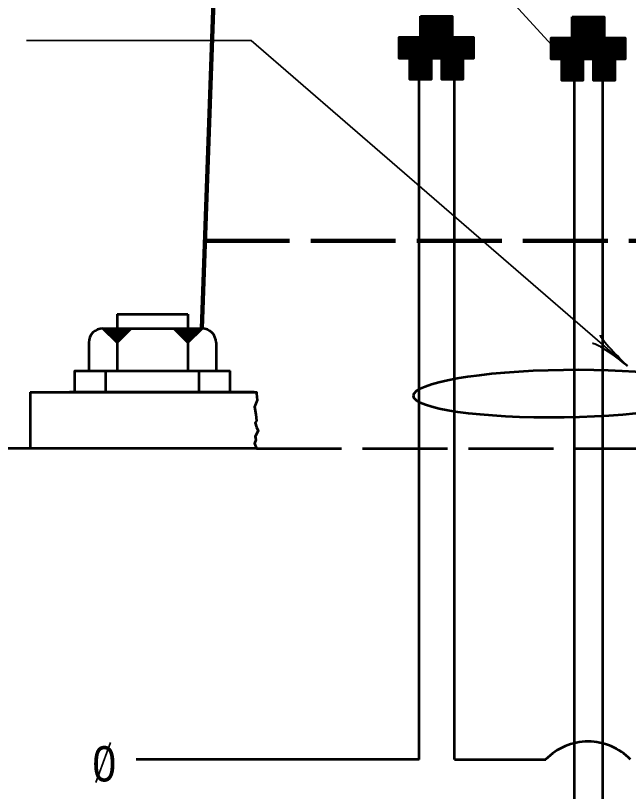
# Model space of a CAD drawing. Extents: x -153 to 527, y -247 to 194.
# Drawn here: x 76.9 to 120.3, y 47.5 to 102.4 of the extents above; entities that cross this region are included whole.
import ezdxf

# ---------------------------------------------------------------- set-up
doc = ezdxf.new("R2010")
doc.units = 0
doc.linetypes.add('LONG_DASHED', pattern=[7.5, 6, -1.5])
doc.layers.add('1', color=7, linetype='Continuous', lineweight=53)

msp = doc.modelspace()

# ---------------------------------------------------------------- linework, layer by layer
at = {"layer": '1', "lineweight": 90}
msp.add_line((90.13, 80.231), (92.956, 161.182), dxfattribs=at)
at = {"layer": '1', "lineweight": 35}
for p, q in [((86.516, 131.404), (114.867, 100.269)), ((93.621, 100.614), (77.712, 100.614)), ((93.621, 100.614), (120.211, 77.581)), ((83.665, 50.928), (82.634, 48.096))]:
    msp.add_line(p, q, dxfattribs=at)
at = {"layer": '1'}
for p, q in [((105.586, 102.186), (107.836, 102.186)), ((116.321, 102.136), (118.571, 102.136)), ((105.586, 102.036), (107.836, 102.036)), ((105.586, 101.861), (107.836, 101.861)), ((105.586, 101.71), (107.836, 101.71)), ((116.321, 101.985), (118.571, 101.985)), ((116.321, 101.81), (118.571, 101.81)), ((116.321, 101.659), (118.571, 101.659)), ((105.586, 101.56), (107.836, 101.56)), ((105.586, 101.384), (107.836, 101.384)), ((105.586, 101.234), (107.836, 101.234)), ((105.586, 101.058), (107.836, 101.058)), ((116.321, 101.509), (118.571, 101.509)), ((116.321, 101.333), (118.571, 101.333)), ((116.321, 101.183), (118.571, 101.183)), ((104.086, 100.732), (105.586, 100.732)), ((104.086, 100.632), (105.586, 100.632)), ((104.086, 100.507), (105.586, 100.507)), ((105.586, 100.883), (107.836, 100.883)), ((105.586, 100.732), (107.836, 100.732)), ((105.586, 100.557), (107.836, 100.557)), ((107.836, 100.782), (109.336, 100.782)), ((107.836, 100.657), (109.336, 100.657)), ((107.836, 100.557), (109.336, 100.557)), ((114.821, 100.682), (116.321, 100.682)), ((114.821, 100.581), (116.321, 100.581)), ((116.321, 101.007), (118.571, 101.007)), ((116.321, 100.832), (118.571, 100.832)), ((116.321, 100.682), (118.571, 100.682)), ((116.321, 100.506), (118.571, 100.506)), ((118.571, 100.732), (120.071, 100.732)), ((118.571, 100.606), (120.071, 100.606)), ((118.571, 100.506), (120.071, 100.506)), ((104.086, 100.356), (105.586, 100.356)), ((104.086, 100.231), (105.586, 100.231)), ((104.086, 100.055), (105.586, 100.055)), ((105.586, 100.431), (107.836, 100.431)), ((105.586, 100.331), (107.836, 100.331)), ((105.586, 100.256), (107.836, 100.256)), ((105.586, 100.206), (107.836, 100.206)), ((105.586, 100.131), (107.836, 100.131)), ((105.586, 99.98), (107.836, 99.98)), ((107.836, 100.406), (109.336, 100.406)), ((107.836, 100.231), (109.336, 100.231)), ((107.836, 100.105), (109.336, 100.105)), ((107.836, 99.955), (109.336, 99.955)), ((114.821, 100.456), (116.321, 100.456)), ((114.821, 100.305), (116.321, 100.305)), ((114.821, 100.18), (116.321, 100.18)), ((114.821, 100.005), (116.321, 100.005)), ((116.321, 100.381), (118.571, 100.381)), ((116.321, 100.28), (118.571, 100.28)), ((116.321, 100.205), (118.571, 100.205)), ((116.321, 100.155), (118.571, 100.155)), ((116.321, 100.08), (118.571, 100.08)), ((118.571, 100.356), (120.071, 100.356)), ((118.571, 100.18), (120.071, 100.18)), ((118.571, 100.055), (120.071, 100.055)), ((104.086, 99.88), (105.586, 99.88)), ((104.086, 99.78), (105.586, 99.78)), ((104.086, 99.654), (105.586, 99.654)), ((104.086, 99.554), (105.586, 99.554)), ((104.086, 99.403), (105.586, 99.403)), ((105.586, 99.905), (107.836, 99.905)), ((105.586, 99.729), (107.836, 99.729)), ((105.586, 99.579), (107.836, 99.579)), ((105.586, 99.454), (107.836, 99.454)), ((107.836, 99.83), (109.336, 99.83)), ((107.836, 99.704), (109.336, 99.704)), ((107.836, 99.579), (109.336, 99.579)), ((107.836, 99.428), (109.336, 99.428)), ((114.821, 99.829), (116.321, 99.829)), ((114.821, 99.729), (116.321, 99.729)), ((114.821, 99.603), (116.321, 99.603)), ((114.821, 99.503), (116.321, 99.503)), ((116.321, 99.929), (118.571, 99.929)), ((116.321, 99.854), (118.571, 99.854)), ((116.321, 99.679), (118.571, 99.679)), ((116.321, 99.528), (118.571, 99.528)), ((116.321, 99.403), (118.571, 99.403)), ((118.571, 99.904), (120.071, 99.904)), ((118.571, 99.779), (120.071, 99.779)), ((118.571, 99.654), (120.071, 99.654)), ((118.571, 99.528), (120.071, 99.528)), ((106.336, 99.328), (104.836, 99.328)), ((106.336, 99.303), (104.836, 99.303)), ((106.336, 99.228), (104.836, 99.228)), ((106.336, 99.128), (104.836, 99.128)), ((106.336, 99.027), (104.836, 99.027)), ((106.336, 98.952), (104.836, 98.952)), ((106.336, 98.902), (104.836, 98.902)), ((106.336, 98.852), (104.836, 98.852)), ((108.586, 99.378), (107.086, 99.378)), ((108.586, 99.328), (107.086, 99.328)), ((108.586, 99.278), (107.086, 99.278)), ((108.586, 99.228), (107.086, 99.228)), ((108.586, 99.153), (107.086, 99.153)), ((108.586, 99.078), (107.086, 99.078)), ((108.586, 99.027), (107.086, 99.027)), ((108.586, 98.977), (107.086, 98.977)), ((108.586, 98.902), (107.086, 98.902)), ((108.586, 98.852), (107.086, 98.852)), ((114.821, 99.353), (116.321, 99.353)), ((117.071, 99.278), (115.571, 99.278)), ((117.071, 99.252), (115.571, 99.252)), ((117.071, 99.177), (115.571, 99.177)), ((117.071, 99.077), (115.571, 99.077)), ((117.071, 98.977), (115.571, 98.977)), ((117.071, 98.901), (115.571, 98.901)), ((117.071, 98.851), (115.571, 98.851)), ((119.321, 99.328), (117.821, 99.328)), ((119.321, 99.278), (117.821, 99.278)), ((119.321, 99.227), (117.821, 99.227)), ((119.321, 99.177), (117.821, 99.177)), ((119.321, 99.102), (117.821, 99.102)), ((119.321, 99.027), (117.821, 99.027)), ((119.321, 98.977), (117.821, 98.977)), ((119.321, 98.926), (117.821, 98.926)), ((119.321, 98.851), (117.821, 98.851)), ((118.571, 99.378), (120.071, 99.378)), ((106.336, 98.752), (104.836, 98.752)), ((106.336, 98.676), (104.836, 98.676)), ((106.336, 98.576), (104.836, 98.576)), ((106.336, 98.476), (104.836, 98.476)), ((106.336, 98.35), (104.836, 98.35)), ((108.586, 98.777), (107.086, 98.777)), ((108.586, 98.727), (107.086, 98.727)), ((108.586, 98.701), (107.086, 98.701)), ((108.586, 98.651), (107.086, 98.651)), ((108.586, 98.626), (107.086, 98.626)), ((108.586, 98.576), (107.086, 98.576)), ((108.586, 98.526), (107.086, 98.526)), ((108.586, 98.476), (107.086, 98.476)), ((108.586, 98.401), (107.086, 98.401)), ((108.586, 98.325), (107.086, 98.325)), ((117.071, 98.801), (115.571, 98.801)), ((117.071, 98.701), (115.571, 98.701)), ((117.071, 98.626), (115.571, 98.626)), ((117.071, 98.525), (115.571, 98.525)), ((117.071, 98.425), (115.571, 98.425)), ((117.071, 98.3), (115.571, 98.3)), ((119.321, 98.801), (117.821, 98.801)), ((119.321, 98.726), (117.821, 98.726)), ((119.321, 98.676), (117.821, 98.676)), ((119.321, 98.651), (117.821, 98.651)), ((119.321, 98.6), (117.821, 98.6)), ((119.321, 98.575), (117.821, 98.575)), ((119.321, 98.525), (117.821, 98.525)), ((119.321, 98.475), (117.821, 98.475)), ((119.321, 98.425), (117.821, 98.425)), ((119.321, 98.35), (117.821, 98.35)), ((106.336, 98.25), (104.836, 98.25)), ((106.336, 98.15), (104.836, 98.15)), ((106.336, 98.049), (104.836, 98.049)), ((106.336, 97.949), (104.836, 97.949)), ((105.488, 49.731), (105.488, 97.837)), ((108.586, 98.25), (107.086, 98.25)), ((108.586, 98.2), (107.086, 98.2)), ((108.586, 98.15), (107.086, 98.15)), ((108.586, 98.1), (107.086, 98.1)), ((108.586, 98.025), (107.086, 98.025)), ((108.586, 97.999), (107.086, 97.999)), ((107.988, 49.731), (107.988, 97.837)), ((117.071, 98.199), (115.571, 98.199)), ((117.071, 98.099), (115.571, 98.099)), ((117.071, 97.999), (115.571, 97.999)), ((117.071, 97.898), (115.571, 97.898)), ((116.488, 43.731), (116.488, 97.786)), ((119.321, 98.275), (117.821, 98.275)), ((119.321, 98.199), (117.821, 98.199)), ((119.321, 98.149), (117.821, 98.149)), ((119.321, 98.099), (117.821, 98.099)), ((119.321, 98.049), (117.821, 98.049)), ((119.321, 97.974), (117.821, 97.974)), ((119.321, 97.949), (117.821, 97.949)), ((118.488, 43.731), (118.488, 97.786)), ((84.13, 81.231), (84.13, 77.231)), ((84.13, 81.231), (89.13, 81.231)), ((89.13, 81.231), (89.13, 77.231)), ((83.13, 80.231), (90.13, 80.231)), ((84.13, 79.231), (83.13, 80.231)), ((83.212, 80.149), (83.295, 80.231)), ((83.225, 80.135), (83.308, 80.218)), ((83.242, 80.118), (83.325, 80.201)), ((83.246, 80.115), (83.328, 80.198)), ((83.25, 80.11), (83.333, 80.193)), ((83.252, 80.109), (83.334, 80.191)), ((83.255, 80.106), (83.337, 80.188)), ((83.261, 80.1), (83.392, 80.231)), ((83.264, 80.097), (83.398, 80.231)), ((83.272, 80.089), (83.414, 80.231)), ((83.275, 80.086), (83.42, 80.231)), ((83.287, 80.073), (83.445, 80.231)), ((83.294, 80.067), (83.458, 80.231)), ((83.303, 80.058), (83.477, 80.231)), ((83.311, 80.05), (83.492, 80.231)), ((83.322, 80.039), (83.514, 80.231)), ((83.333, 80.028), (83.536, 80.231)), ((83.337, 80.023), (83.545, 80.231)), ((83.345, 80.015), (83.561, 80.231)), ((83.35, 80.011), (83.571, 80.231)), ((83.35, 80.011), (83.571, 80.231)), ((83.356, 80.004), (83.583, 80.231)), ((83.361, 80), (83.593, 80.231)), ((83.37, 79.99), (83.611, 80.231)), ((83.382, 79.979), (83.633, 80.231)), ((83.391, 79.97), (83.652, 80.231)), ((83.394, 79.967), (83.659, 80.231)), ((83.408, 79.953), (83.687, 80.231)), ((83.419, 79.942), (83.709, 80.231)), ((83.428, 79.932), (83.727, 80.231)), ((83.436, 79.924), (83.743, 80.231)), ((83.438, 79.923), (83.746, 80.231)), ((83.449, 79.912), (83.768, 80.231)), ((83.457, 79.904), (83.784, 80.231)), ((83.465, 79.896), (83.799, 80.231)), ((83.471, 79.89), (83.812, 80.231)), ((83.476, 79.885), (83.822, 80.231)), ((83.486, 79.874), (83.843, 80.231)), ((83.491, 79.87), (83.853, 80.231)), ((83.496, 79.865), (83.862, 80.231)), ((83.51, 79.851), (83.89, 80.231)), ((83.513, 79.848), (83.897, 80.231)), ((83.516, 79.844), (83.903, 80.231)), ((83.524, 79.837), (83.919, 80.231)), ((83.535, 79.826), (83.941, 80.231)), ((83.54, 79.821), (83.95, 80.231)), ((83.546, 79.815), (83.963, 80.231)), ((83.551, 79.81), (83.972, 80.231)), ((83.557, 79.804), (83.984, 80.231)), ((83.56, 79.801), (83.991, 80.231)), ((83.566, 79.794), (84.003, 80.231)), ((83.579, 79.782), (84.028, 80.231)), ((83.588, 79.772), (84.047, 80.231)), ((83.591, 79.769), (84.053, 80.231)), ((83.606, 79.755), (84.082, 80.231)), ((83.606, 79.755), (84.082, 80.231)), ((83.609, 79.752), (84.088, 80.231)), ((83.612, 79.749), (84.094, 80.231)), ((83.615, 79.746), (84.1, 80.231)), ((83.621, 79.739), (84.113, 80.231)), ((83.626, 79.735), (84.122, 80.231)), ((83.626, 79.735), (84.122, 80.231)), ((83.634, 79.727), (84.138, 80.231)), ((83.643, 79.718), (84.157, 80.231)), ((83.648, 79.713), (84.166, 80.231)), ((83.653, 79.708), (84.176, 80.231)), ((83.656, 79.705), (84.182, 80.231)), ((83.657, 79.703), (84.185, 80.231)), ((83.66, 79.7), (84.191, 80.231)), ((83.671, 79.689), (84.213, 80.231)), ((83.684, 79.677), (84.238, 80.231)), ((83.692, 79.669), (84.254, 80.231)), ((83.698, 79.663), (84.267, 80.231)), ((83.709, 79.652), (84.289, 80.231)), ((83.714, 79.647), (84.298, 80.231)), ((83.714, 79.647), (84.298, 80.231)), ((83.717, 79.644), (84.304, 80.231)), ((83.717, 79.644), (84.304, 80.231)), ((83.723, 79.638), (84.317, 80.231)), ((83.73, 79.631), (84.329, 80.231)), ((83.737, 79.623), (84.345, 80.231)), ((83.75, 79.611), (84.37, 80.231)), ((83.756, 79.605), (84.383, 80.231)), ((83.762, 79.598), (84.395, 80.231)), ((83.764, 79.597), (84.398, 80.231)), ((83.77, 79.59), (84.411, 80.231)), ((83.78, 79.581), (84.429, 80.231)), ((83.789, 79.572), (84.448, 80.231)), ((83.797, 79.564), (84.464, 80.231)), ((83.801, 79.559), (84.473, 80.231)), ((83.806, 79.555), (84.483, 80.231)), ((83.809, 79.551), (84.489, 80.231)), ((83.82, 79.54), (84.511, 80.231)), ((83.825, 79.536), (84.52, 80.231)), ((83.827, 79.534), (84.468, 80.174)), ((83.828, 79.533), (84.527, 80.231)), ((83.836, 79.525), (84.542, 80.231)), ((83.839, 79.522), (84.548, 80.231)), ((83.839, 79.522), (84.549, 80.231)), ((83.842, 79.518), (84.555, 80.231)), ((83.852, 79.509), (84.574, 80.231)), ((83.866, 79.495), (84.602, 80.231)), ((83.871, 79.49), (84.612, 80.231)), ((83.882, 79.479), (84.633, 80.231)), ((83.888, 79.473), (84.646, 80.231)), ((83.897, 79.464), (84.665, 80.231)), ((83.902, 79.459), (84.674, 80.231)), ((83.907, 79.454), (84.684, 80.231)), ((83.911, 79.45), (84.693, 80.231)), ((83.918, 79.443), (84.706, 80.231)), ((83.925, 79.435), (84.721, 80.231)), ((83.936, 79.424), (84.743, 80.231)), ((83.939, 79.421), (84.749, 80.231)), ((83.952, 79.409), (84.774, 80.231)), ((83.961, 79.399), (84.793, 80.231)), ((83.966, 79.395), (84.803, 80.231)), ((83.969, 79.391), (84.809, 80.231)), ((83.982, 79.379), (84.834, 80.231)), ((83.991, 79.37), (84.853, 80.231)), ((83.996, 79.365), (84.862, 80.231)), ((84.002, 79.359), (84.874, 80.231)), ((84.005, 79.355), (84.881, 80.231)), ((84.008, 79.352), (84.887, 80.231)), ((84.018, 79.343), (84.906, 80.231)), ((84.019, 79.341), (84.909, 80.231)), ((84.027, 79.334), (84.924, 80.231)), ((84.027, 79.334), (84.925, 80.231)), ((84.038, 79.322), (84.947, 80.231)), ((84.043, 79.318), (84.956, 80.231)), ((84.054, 79.307), (84.978, 80.231)), ((84.055, 79.305), (84.981, 80.231)), ((84.071, 79.29), (85.013, 80.231)), ((84.077, 79.283), (85.025, 80.231)), ((84.09, 79.271), (85.05, 80.231)), ((84.102, 79.258), (85.075, 80.231)), ((84.102, 79.258), (85.075, 80.231)), ((84.115, 79.246), (85.1, 80.231)), ((84.13, 79.231), (85.13, 80.231)), ((89.13, 79.231), (88.13, 80.231)), ((89.136, 79.228), (88.136, 80.228)), ((88.149, 80.216), (88.164, 80.231)), ((88.163, 80.202), (88.192, 80.231)), ((88.175, 80.189), (88.217, 80.231)), ((88.181, 80.183), (88.23, 80.231)), ((88.191, 80.174), (88.248, 80.231)), ((88.202, 80.163), (88.27, 80.231)), ((88.211, 80.153), (88.289, 80.231)), ((88.216, 80.148), (88.298, 80.231)), ((88.219, 80.145), (88.302, 80.228)), ((88.232, 80.133), (88.33, 80.231)), ((88.239, 80.125), (88.322, 80.207)), ((88.242, 80.122), (88.325, 80.204)), ((88.249, 80.116), (88.364, 80.231)), ((88.252, 80.112), (88.371, 80.231)), ((88.252, 80.112), (88.335, 80.194)), ((88.257, 80.107), (88.34, 80.19)), ((88.268, 80.097), (88.402, 80.231)), ((88.274, 80.09), (88.415, 80.231)), ((88.282, 80.083), (88.43, 80.231)), ((88.288, 80.076), (88.443, 80.231)), ((88.294, 80.07), (88.452, 80.228)), ((88.301, 80.064), (88.468, 80.231)), ((88.311, 80.053), (88.49, 80.231)), ((88.322, 80.042), (88.512, 80.231)), ((88.324, 80.04), (88.515, 80.231)), ((88.327, 80.037), (88.521, 80.231)), ((88.329, 80.036), (88.524, 80.231)), ((88.332, 80.032), (88.531, 80.231)), ((88.337, 80.027), (88.541, 80.231)), ((88.344, 80.02), (88.552, 80.228)), ((88.357, 80.007), (88.577, 80.228)), ((88.377, 79.987), (88.618, 80.228)), ((88.382, 79.982), (88.631, 80.231)), ((88.388, 79.976), (88.64, 80.228)), ((88.393, 79.971), (88.653, 80.231)), ((88.395, 79.97), (88.656, 80.231)), ((88.401, 79.964), (88.668, 80.231)), ((88.404, 79.96), (88.675, 80.231)), ((88.415, 79.949), (88.697, 80.231)), ((88.415, 79.949), (88.694, 80.228)), ((88.42, 79.945), (88.706, 80.231)), ((88.426, 79.938), (88.719, 80.231)), ((88.429, 79.935), (88.725, 80.231)), ((88.44, 79.924), (88.747, 80.231)), ((88.445, 79.92), (88.756, 80.231)), ((88.446, 79.918), (88.759, 80.231)), ((88.456, 79.909), (88.778, 80.231)), ((88.459, 79.906), (88.785, 80.231)), ((88.464, 79.901), (88.794, 80.231)), ((88.464, 79.901), (88.753, 80.19)), ((88.478, 79.887), (88.822, 80.231)), ((88.486, 79.879), (88.838, 80.231)), ((88.489, 79.876), (88.844, 80.231)), ((88.495, 79.87), (88.857, 80.231)), ((88.498, 79.866), (88.86, 80.228)), ((88.501, 79.863), (88.869, 80.231)), ((88.503, 79.862), (88.869, 80.228)), ((88.52, 79.844), (88.903, 80.228)), ((88.529, 79.835), (88.926, 80.231)), ((88.536, 79.829), (88.938, 80.231)), ((88.544, 79.821), (88.954, 80.231)), ((88.547, 79.818), (88.957, 80.228)), ((88.557, 79.807), (88.978, 80.228)), ((88.558, 79.807), (88.982, 80.231)), ((88.569, 79.796), (89.004, 80.231)), ((88.573, 79.791), (89.01, 80.228)), ((88.58, 79.785), (89.026, 80.231)), ((88.586, 79.779), (89.035, 80.228)), ((88.592, 79.772), (89.051, 80.231)), ((88.6, 79.764), (89.067, 80.231)), ((88.606, 79.758), (89.079, 80.231)), ((88.609, 79.755), (89.086, 80.231)), ((88.612, 79.752), (89.092, 80.231)), ((88.616, 79.749), (89.095, 80.228)), ((88.62, 79.744), (89.099, 80.223)), ((88.622, 79.743), (89.11, 80.231)), ((88.633, 79.732), (89.129, 80.228)), ((88.633, 79.732), (89.129, 80.228)), ((88.636, 79.728), (89.139, 80.231)), ((88.641, 79.724), (89.148, 80.231)), ((88.645, 79.719), (89.158, 80.231)), ((88.658, 79.706), (89.183, 80.231)), ((88.659, 79.705), (89.186, 80.231)), ((88.669, 79.695), (89.205, 80.231)), ((88.678, 79.686), (89.22, 80.228)), ((88.685, 79.68), (89.236, 80.231)), ((88.694, 79.67), (89.255, 80.231)), ((88.699, 79.666), (89.264, 80.231)), ((88.705, 79.659), (89.273, 80.228)), ((88.707, 79.658), (89.28, 80.231)), ((88.713, 79.651), (89.293, 80.231)), ((88.721, 79.644), (89.308, 80.231)), ((88.721, 79.644), (89.304, 80.228)), ((88.722, 79.642), (89.311, 80.231)), ((88.73, 79.634), (89.327, 80.231)), ((88.735, 79.63), (89.336, 80.231)), ((88.736, 79.628), (89.336, 80.228)), ((88.741, 79.623), (89.349, 80.231)), ((88.741, 79.623), (89.349, 80.231)), ((88.744, 79.62), (89.352, 80.228)), ((88.746, 79.619), (89.358, 80.231)), ((88.747, 79.617), (89.361, 80.231)), ((88.755, 79.609), (89.377, 80.231)), ((88.771, 79.594), (89.405, 80.228)), ((88.777, 79.587), (89.418, 80.228)), ((88.779, 79.586), (89.424, 80.231)), ((88.785, 79.579), (89.435, 80.229)), ((88.786, 79.578), (89.436, 80.228)), ((88.798, 79.567), (89.447, 80.217)), ((88.807, 79.557), (89.457, 80.207)), ((88.808, 79.556), (89.48, 80.228)), ((88.829, 79.535), (89.479, 80.185)), ((88.835, 79.529), (89.534, 80.228)), ((88.841, 79.523), (89.55, 80.231)), ((88.846, 79.519), (89.555, 80.228)), ((88.854, 79.51), (89.575, 80.231)), ((88.859, 79.506), (89.581, 80.228)), ((88.865, 79.499), (89.597, 80.231)), ((88.87, 79.495), (89.606, 80.231)), ((88.881, 79.484), (89.628, 80.231)), ((88.893, 79.471), (89.653, 80.231)), ((88.895, 79.47), (89.653, 80.228)), ((88.903, 79.462), (89.675, 80.234)), ((88.904, 79.46), (89.671, 80.228)), ((88.907, 79.457), (89.681, 80.231)), ((88.909, 79.456), (89.681, 80.228)), ((88.912, 79.453), (89.691, 80.231)), ((88.923, 79.441), (89.713, 80.231)), ((88.932, 79.432), (89.728, 80.228)), ((88.942, 79.423), (89.75, 80.231)), ((88.943, 79.421), (89.75, 80.228)), ((88.946, 79.418), (89.756, 80.228)), ((88.948, 79.416), (89.763, 80.231)), ((88.959, 79.406), (89.781, 80.228)), ((88.961, 79.404), (89.788, 80.231)), ((88.968, 79.396), (89.8, 80.228)), ((88.973, 79.391), (89.809, 80.228)), ((88.976, 79.388), (89.816, 80.228)), ((88.978, 79.387), (89.822, 80.231)), ((88.989, 79.376), (89.841, 80.228)), ((88.998, 79.366), (89.86, 80.228)), ((89.001, 79.363), (89.869, 80.231)), ((89.009, 79.356), (89.881, 80.228)), ((89.011, 79.354), (89.883, 80.226)), ((89.014, 79.351), (89.886, 80.223)), ((89.023, 79.341), (89.896, 80.213)), ((89.025, 79.34), (89.913, 80.228)), ((89.026, 79.338), (89.916, 80.228)), ((89.034, 79.331), (89.931, 80.228)), ((89.044, 79.321), (89.916, 80.193)), ((89.045, 79.319), (89.954, 80.228)), ((89.048, 79.316), (89.921, 80.188)), ((89.05, 79.315), (89.963, 80.228)), ((89.053, 79.311), (89.925, 80.184)), ((89.061, 79.304), (89.985, 80.228)), ((89.061, 79.303), (89.933, 80.176)), ((89.061, 79.303), (89.933, 80.176)), ((89.062, 79.302), (89.988, 80.228)), ((89.062, 79.302), (89.935, 80.174)), ((89.064, 79.3), (89.995, 80.231)), ((89.067, 79.297), (89.94, 80.17)), ((89.075, 79.289), (90.017, 80.231)), ((89.078, 79.286), (90.019, 80.228)), ((89.084, 79.28), (90.032, 80.228)), ((89.097, 79.268), (90.057, 80.228)), ((89.109, 79.255), (90.085, 80.231)), ((89.109, 79.255), (90.082, 80.228)), ((89.122, 79.243), (90.107, 80.228)), ((89.13, 79.231), (90.13, 80.231)), ((89.136, 79.228), (90.136, 80.228)), ((83.285, 80.076), (83.367, 80.158)), ((83.296, 80.065), (83.378, 80.147)), ((83.307, 80.054), (83.389, 80.136)), ((83.31, 80.051), (83.392, 80.133)), ((83.325, 80.035), (83.408, 80.118)), ((83.33, 80.031), (83.413, 80.113)), ((83.338, 80.023), (83.421, 80.105)), ((83.341, 80.019), (83.424, 80.102)), ((83.347, 80.013), (83.43, 80.096)), ((83.379, 79.982), (83.461, 80.064)), ((83.39, 79.971), (83.472, 80.053)), ((83.396, 79.965), (83.478, 80.047)), ((83.399, 79.962), (83.482, 80.044)), ((83.402, 79.958), (83.485, 80.041)), ((83.407, 79.954), (83.489, 80.036)), ((83.416, 79.944), (83.499, 80.027)), ((83.429, 79.932), (83.511, 80.014)), ((83.451, 79.91), (83.533, 79.992)), ((83.48, 79.88), (83.563, 79.962)), ((83.49, 79.871), (83.572, 79.953)), ((83.513, 79.847), (83.596, 79.93)), ((83.523, 79.838), (83.605, 79.92)), ((83.535, 79.825), (83.618, 79.907)), ((83.543, 79.817), (83.626, 79.9)), ((83.565, 79.795), (83.648, 79.878)), ((83.57, 79.791), (83.652, 79.873)), ((83.585, 79.775), (83.668, 79.857)), ((83.585, 79.775), (83.668, 79.857)), ((83.603, 79.758), (83.685, 79.84)), ((83.618, 79.742), (83.701, 79.825)), ((83.635, 79.725), (83.718, 79.807)), ((83.643, 79.717), (83.726, 79.799)), ((83.656, 79.704), (83.739, 79.787)), ((83.684, 79.676), (83.767, 79.759)), ((83.687, 79.673), (83.77, 79.755)), ((83.708, 79.653), (83.79, 79.735)), ((83.72, 79.64), (83.803, 79.723)), ((83.734, 79.626), (83.817, 79.709)), ((83.744, 79.617), (83.826, 79.699)), ((83.753, 79.607), (83.836, 79.69)), ((83.78, 79.58), (83.862, 79.663)), ((83.806, 79.554), (83.889, 79.636)), ((83.814, 79.546), (83.897, 79.629)), ((88.279, 80.086), (88.361, 80.168)), ((88.292, 80.073), (88.374, 80.155)), ((88.302, 80.062), (88.385, 80.144)), ((88.414, 79.95), (88.496, 80.033)), ((88.487, 79.877), (88.57, 79.959)), ((88.503, 79.862), (88.792, 80.151)), ((88.55, 79.814), (88.633, 79.897)), ((88.592, 79.772), (88.675, 79.854)), ((88.609, 79.754), (88.692, 79.837)), ((88.663, 79.701), (88.745, 79.784)), ((88.727, 79.637), (88.81, 79.719)), ((88.787, 79.577), (88.869, 79.66)), ((88.846, 79.518), (89.496, 80.168)), ((88.863, 79.501), (89.513, 80.151)), ((88.871, 79.493), (89.521, 80.143)), ((88.898, 79.466), (89.548, 80.116)), ((89.083, 79.282), (89.955, 80.154)), ((82.13, 79.231), (82.13, 77.231)), ((83.839, 79.521), (83.922, 79.603)), ((83.866, 79.494), (83.948, 79.577)), ((83.966, 79.394), (84.049, 79.476)), ((84.002, 79.358), (84.085, 79.44)), ((84.088, 79.272), (84.171, 79.354)), ((88.846, 79.518), (88.929, 79.6)), ((88.873, 79.491), (88.955, 79.574)), ((88.902, 79.461), (88.985, 79.544)), ((88.94, 79.424), (89.023, 79.506)), ((88.973, 79.391), (89.055, 79.473)), ((89.009, 79.355), (89.092, 79.437)), ((89.023, 79.341), (89.106, 79.423)), ((89.087, 79.276), (89.17, 79.359)), ((91.13, 79.231), (91.13, 77.231)), ((83.321, 75.731), (83.321, 77.231)), ((89.932, 75.731), (89.932, 77.231)), ((92.13, 75.731), (92.13, 77.231)), ((77.988, 75.731), (77.988, 71.731)), ((77.988, 75.731), (80.767, 75.731)), ((93.828, 75.731), (80.767, 75.731)), ((93.988, 71.731), (47.988, 71.731)), ((105.488, 49.731), (85.488, 49.731)), ((107.988, 49.731), (114.438, 49.731))]:
    msp.add_line(p, q, dxfattribs=at)
at = {"layer": '1', "linetype": 'LONG_DASHED', "lineweight": 90}
msp.add_line((90.328, 86.427), (136.109, 86.427), dxfattribs=at)
at = {"layer": '1', "linetype": 'LONG_DASHED'}
msp.add_line((93.988, 71.731), (131.488, 71.731), dxfattribs=at)
at = {"layer": '1'}
for points in [[(105.586, 102.337), (107.836, 102.337), (107.836, 100.837), (109.336, 100.837), (109.336, 99.337), (108.586, 99.337), (108.586, 97.837), (107.086, 97.837), (107.086, 99.337), (106.336, 99.337), (106.336, 97.837), (104.836, 97.837), (104.836, 99.337), (104.086, 99.337), (104.086, 100.837), (105.586, 100.837)], [(116.321, 102.286), (118.571, 102.286), (118.571, 100.786), (120.071, 100.786), (120.071, 99.286), (119.321, 99.286), (119.321, 97.786), (117.821, 97.786), (117.821, 99.286), (117.071, 99.286), (117.071, 97.786), (115.571, 97.786), (115.571, 99.286), (114.821, 99.286), (114.821, 100.786), (116.321, 100.786)]]:
    msp.add_lwpolyline(points, close=True, dxfattribs=at)
for points in [[(81.13, 75.731), (81.13, 77.231), (92.13, 77.231)], [(80.767, 75.731), (93.988, 75.731), (93.998, 75.629)], [(93.998, 75.629), (94.044, 75.145), (93.843, 74.693), (93.943, 74.142), (93.993, 73.69), (93.893, 73.54), (93.993, 73.239), (94.094, 72.988), (93.893, 72.587), (93.943, 72.336), (93.843, 72.085), (93.988, 71.731)]]:
    msp.add_lwpolyline(points, dxfattribs=at)
for centre, radius, start, end in [((83.13, 79.231), 1, 90, 180), ((90.13, 79.231), 1, 0, 90), ((117.438, 46.802), 4.193, 44.3118, 135.7181)]:
    msp.add_arc(centre, radius, start, end, dxfattribs=at)
at = {"layer": '1', "lineweight": 40}
for centre, major_axis, ratio, start_param, end_param in [((119.502, 78.475), (-1.213, 1.283), 0.07063, 6.282307, 8.559703), ((119.205, 78.087), (1.452, -1.051), 0.122415, 0.896353, 3.141593)]:
    msp.add_ellipse(centre, major_axis=major_axis, ratio=ratio, start_param=start_param, end_param=end_param, dxfattribs=at)
at = {"layer": '1'}
msp.add_ellipse((115.722, 75.62), major_axis=(-10.639, -0.159), ratio=0.158809, dxfattribs=at)

# ---------------------------------------------------------------- texts
at = {"layer": '1', "width": 0.9}
msp.add_text('0', height=2.5, dxfattribs=at).set_placement((82.387, 48.169))

doc.saveas('drawing.dxf')
